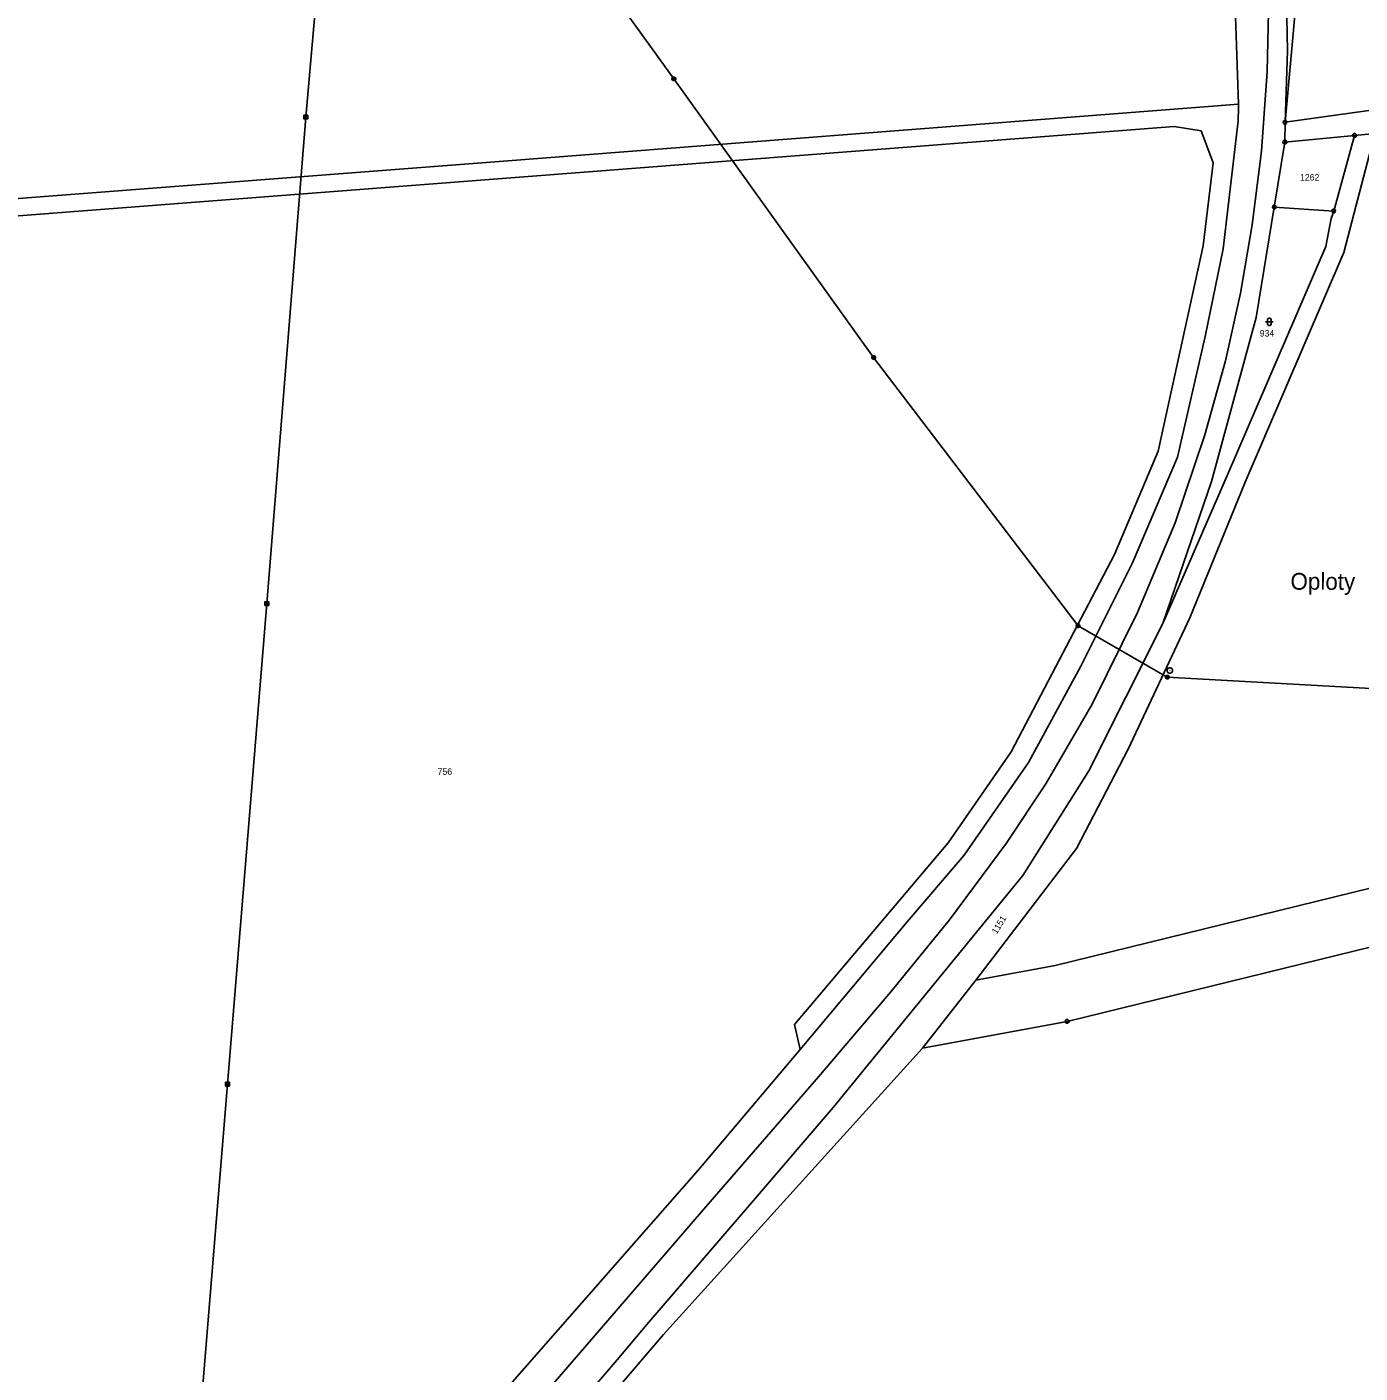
# Model space of a CAD drawing. Extents: x -812394 to -807601, y -1013098 to -1009266.
# Drawn here: x -809615.2 to -809265.1, y -1011988.8 to -1011635.2 of the extents above; entities that cross this region are included whole.
import ezdxf

# ---------------------------------------------------------------- set-up
doc = ezdxf.new("R2010")
doc.units = 0
for name, color, linetype in [('KN_HRANICE', 7, 'Continuous'), ('KN_KULTURY', 7, 'Continuous'), ('KN_MEZNIKY', 7, 'Continuous'), ('KN_PARCELY', 7, 'Continuous'), ('KN_VEDENI', 7, 'Continuous')]:
    doc.layers.add(name, color=color, linetype=linetype)

# ---------------------------------------------------------------- blocks, each defined once
blk = doc.blocks.new('101')
blk.add_line((-0.05, 0), (0.05, 0))
blk.add_lwpolyline([(0.19, 0.72), (0.53, 0.53), (0.72, 0.19), (0.72, -0.2), (0.53, -0.54), (0.19, -0.73), (-0.2, -0.73), (-0.54, -0.54), (-0.73, -0.2), (-0.73, 0.19), (-0.54, 0.53), (-0.2, 0.72), (0.19, 0.72)])
blk = doc.blocks.new('316')
for points in [[(-1, 1), (0.27, 1), (1, 1)], [(-0.5, 1.5), (-0.4, 1.79), (-0.15, 1.97), (0.16, 1.97), (0.41, 1.79), (0.51, 1.5), (0.51, 0.5), (0.41, 0.21), (0.16, 0.03), (-0.15, 0.03), (-0.4, 0.21), (-0.5, 0.5), (-0.5, 1.5)]]:
    blk.add_lwpolyline(points)
blk = doc.blocks.new('105')
blk.add_line((-0.12, 0), (0.12, 0))
blk.add_lwpolyline([(0.15, 0.48), (0.4, 0.3), (0.5, 0.01), (0.4, -0.28), (0.15, -0.46), (-0.16, -0.46), (-0.41, -0.28), (-0.51, 0.01), (-0.41, 0.3), (-0.16, 0.48), (0.15, 0.48)])
blk = doc.blocks.new('601')
blk.add_lwpolyline([(-0.15, 0.48), (0.16, 0.48), (0.41, 0.3), (0.51, 0.01), (0.41, -0.28), (0.16, -0.46), (-0.15, -0.46), (-0.4, -0.28), (-0.5, 0.01), (-0.4, 0.3), (-0.15, 0.48), (-0.12, 0.44), (0.12, 0.44), (0.28, 0.36), (-0.28, 0.36), (-0.36, 0.28), (0.36, 0.28), (0.36, 0.2), (-0.36, 0.2), (-0.4, 0.12), (0.4, 0.12), (0.44, 0.04), (-0.44, 0.04), (-0.44, -0.04), (0.44, -0.04), (0.41, -0.12), (-0.4, -0.12), (-0.39, -0.2), (0.42, -0.2), (0.37, -0.28), (-0.35, -0.28), (-0.27, -0.36), (0.29, -0.36), (0.18, -0.44), (-0.16, -0.44)])
blk = doc.blocks.new('602')
blk.add_lwpolyline([(-0.5, 0.5), (0.5, 0.5), (0.5, -0.5), (-0.5, -0.5), (-0.5, 0.5), (-0.44, 0.44), (0.44, 0.44), (0.44, 0.36), (-0.44, 0.36), (-0.44, 0.28), (0.44, 0.28), (0.44, 0.2), (-0.44, 0.2), (-0.44, 0.12), (0.44, 0.12), (0.44, 0.04), (-0.44, 0.04), (-0.44, -0.04), (0.44, -0.04), (0.44, -0.12), (-0.44, -0.12), (-0.44, -0.2), (0.44, -0.2), (0.44, -0.28), (-0.44, -0.28), (-0.44, -0.36), (0.44, -0.36), (0.44, -0.44), (-0.44, -0.44)])

msp = doc.modelspace()

# ---------------------------------------------------------------- linework, layer by layer
at = {"layer": 'KN_HRANICE'}
for p, q in [((-809297.03, -1011655.51), (-809299, -1011599.04)), ((-809280.7, -1011614.9), (-809284.79, -1011660.24)), ((-809297.03, -1011655.51), (-809489.99, -1011670.42)), ((-809297.04, -1011656.44), (-809297.03, -1011655.51)), ((-809240.39, -1011653.93), (-809284.79, -1011660.24)), ((-809297.07, -1011659.82), (-809297.04, -1011656.44)), ((-809483.55, -1011674.44), (-809313.91, -1011661.33)), ((-809313.91, -1011661.33), (-809306.83, -1011662.51)), ((-809306.83, -1011662.51), (-809303.7, -1011670.85)), ((-809301.03, -1011693.5), (-809297.07, -1011659.82)), ((-809284.79, -1011660.24), (-809284.85, -1011665.44)), ((-809266.53, -1011663.7), (-809262.03, -1011663.27)), ((-809284.85, -1011665.44), (-809287.62, -1011682.5)), ((-809284.85, -1011665.44), (-809266.53, -1011663.7)), ((-809272.02, -1011683.54), (-809266.53, -1011663.7)), ((-809269.33, -1011694.44), (-809262.63, -1011668.57)), ((-809489.99, -1011670.42), (-809682.95, -1011685.34)), ((-809303.7, -1011670.85), (-809306.27, -1011692.65)), ((-809653.19, -1011687.55), (-809483.55, -1011674.44)), ((-809287.62, -1011682.5), (-809292.41, -1011711.48)), ((-809287.62, -1011682.5), (-809272.02, -1011683.54)), ((-809272.02, -1011683.54), (-809272.71, -1011685.54)), ((-809272.71, -1011685.54), (-809274.07, -1011692.82)), ((-809306.27, -1011692.65), (-809318.07, -1011746.59)), ((-809305.77, -1011716.47), (-809301.03, -1011693.5)), ((-809274.07, -1011692.82), (-809299.89, -1011752.83)), ((-809295.27, -1011754.76), (-809269.33, -1011694.44)), ((-809313.01, -1011748.23), (-809305.77, -1011716.47)), ((-809318.07, -1011746.59), (-809329.62, -1011773.73)), ((-809324.81, -1011775.96), (-809313.01, -1011748.23)), ((-809299.89, -1011752.83), (-809316.9, -1011791.9)), ((-809309.78, -1011790.4), (-809295.27, -1011754.76)), ((-809329.62, -1011773.73), (-809356.71, -1011825.61)), ((-809338.46, -1011803.06), (-809324.81, -1011775.96)), ((-809325.96, -1011824.92), (-809309.78, -1011790.4)), ((-809352.19, -1011828.39), (-809338.46, -1011803.06)), ((-809356.71, -1011825.61), (-809373.26, -1011849.47)), ((-809339.54, -1011851.01), (-809325.96, -1011824.92)), ((-809369.05, -1011852.71), (-809352.19, -1011828.39)), ((-809164.04, -1011837.22), (-809345.17, -1011881.72)), ((-809373.26, -1011849.47), (-809413.57, -1011897.19)), ((-809384.02, -1011870.28), (-809369.05, -1011852.71)), ((-809366.02, -1011885.56), (-809339.54, -1011851.01)), ((-809186.95, -1011858.3), (-809342.02, -1011896.39)), ((-809412.15, -1011903.73), (-809384.02, -1011870.28)), ((-809345.17, -1011881.72), (-809366.02, -1011885.56)), ((-809379.96, -1011903.38), (-809366.02, -1011885.56)), ((-809342.02, -1011896.39), (-809379.96, -1011903.38)), ((-809413.57, -1011897.19), (-809412.15, -1011903.73)), ((-809448.03, -1011978.61), (-809379.96, -1011903.38)), ((-809438.78, -1011935.4), (-809412.15, -1011903.73)), ((-809509.29, -1012015.64), (-809438.78, -1011935.4)), ((-809451.84, -1011975.37), (-809460.19, -1011985.3)), ((-809459.78, -1011992.49), (-809448.03, -1011978.61)), ((-809460.19, -1011985.3), (-809469.21, -1011995.78))]:
    msp.add_line(p, q, dxfattribs=at)
for points in [[(-809324.88, -1011455.39), (-809308.72, -1011492.09), (-809297.73, -1011528.14), (-809289.72, -1011565.01), (-809284.91, -1011602.46), (-809284.17, -1011641.38), (-809284.79, -1011660.24)], [(-809292.41, -1011711.48), (-809304.11, -1011754.57), (-809316.9, -1011791.9)], [(-809316.9, -1011791.9), (-809336.32, -1011830.6), (-809353.61, -1011858.09), (-809393.32, -1011906.59), (-809403.42, -1011918.99), (-809425.45, -1011944.64), (-809451.84, -1011975.37)]]:
    msp.add_lwpolyline(points, dxfattribs=at)
at = {"layer": 'KN_VEDENI'}
for p, q in [((-809289.48, -1011646.86), (-809289.06, -1011626.46)), ((-809290.94, -1011667.83), (-809289.48, -1011646.86)), ((-809293.41, -1011687.13), (-809290.94, -1011667.83)), ((-809296.52, -1011705.09), (-809293.41, -1011687.13)), ((-809300.47, -1011722.88), (-809296.52, -1011705.09)), ((-809305.86, -1011742.33), (-809300.47, -1011722.88)), ((-809313.67, -1011765.4), (-809305.86, -1011742.33)), ((-809323.5, -1011788.98), (-809313.67, -1011765.4)), ((-809335.43, -1011813.05), (-809323.5, -1011788.98)), ((-809347.63, -1011834), (-809335.43, -1011813.05)), ((-809358.06, -1011849.7), (-809347.63, -1011834)), ((-809372.92, -1011869.73), (-809358.06, -1011849.7)), ((-809388.31, -1011888.63), (-809372.92, -1011869.73)), ((-809407.28, -1011910.95), (-809388.31, -1011888.63)), ((-809438.04, -1011946.41), (-809407.28, -1011910.95)), ((-809468.7, -1011981.96), (-809438.04, -1011946.41)), ((-809502.99, -1012021.62), (-809468.7, -1011981.96))]:
    msp.add_line(p, q, dxfattribs=at)
for points in [[(-809530.59, -1011529.94), (-809541.94, -1011658.87), (-809552.16, -1011786.65), (-809562.51, -1011912.86), (-809572.93, -1012039.98), (-809584.61, -1012181.8), (-809595.17, -1012312.56), (-809605.96, -1012440.15), (-809606.04, -1012441.12)], [(-809530.59, -1011529.94), (-809514.36, -1011553.41), (-809497.68, -1011576.04), (-809445.29, -1011648.83), (-809392.83, -1011722.03), (-809339.15, -1011792.47), (-809315.72, -1011805.98), (-809222.8, -1011811.11), (-809172.21, -1011812.31), (-809130.54, -1011813.9), (-809115.78, -1011814.07)]]:
    msp.add_lwpolyline(points, dxfattribs=at)

# ---------------------------------------------------------------- block references
at = {"layer": 'KN_KULTURY'}
msp.add_blockref('316', (-809288.91, -1011713.66), dxfattribs=at)
at = {"layer": 'KN_MEZNIKY'}
for name, p in [('105', (-809284.79, -1011660.24)), ('105', (-809266.53, -1011663.7)), ('105', (-809284.85, -1011665.44)), ('105', (-809287.62, -1011682.5)), ('105', (-809272.02, -1011683.54)), ('101', (-809315.04, -1011804.22)), ('105', (-809342.02, -1011896.39))]:
    msp.add_blockref(name, p, dxfattribs=at)
at = {"layer": 'KN_VEDENI'}
for name, p in [('601', (-809445.29, -1011648.83)), ('602', (-809541.94, -1011658.87)), ('601', (-809392.83, -1011722.03)), ('602', (-809552.16, -1011786.65)), ('601', (-809339.15, -1011792.47)), ('601', (-809315.72, -1011805.98)), ('602', (-809562.51, -1011912.86))]:
    msp.add_blockref(name, p, dxfattribs=at)

# ---------------------------------------------------------------- texts
at = {"layer": 'KN_PARCELY'}
for s, p in [('1262', (-809280.85, -1011675.54)), ('934', (-809291.44, -1011716.51)), ('756', (-809507.32, -1011831.63))]:
    msp.add_text(s, height=1.7, dxfattribs=at).set_placement(p)
for s, height, rotation, p in [('Oploty', 4.4, 359.817, (-809283.38, -1011783)), ('1151', 1.7, 58.843, (-809360.49, -1011873.61))]:
    msp.add_text(s, height=height, rotation=rotation, dxfattribs=at).set_placement(p)

doc.saveas('drawing.dxf')
